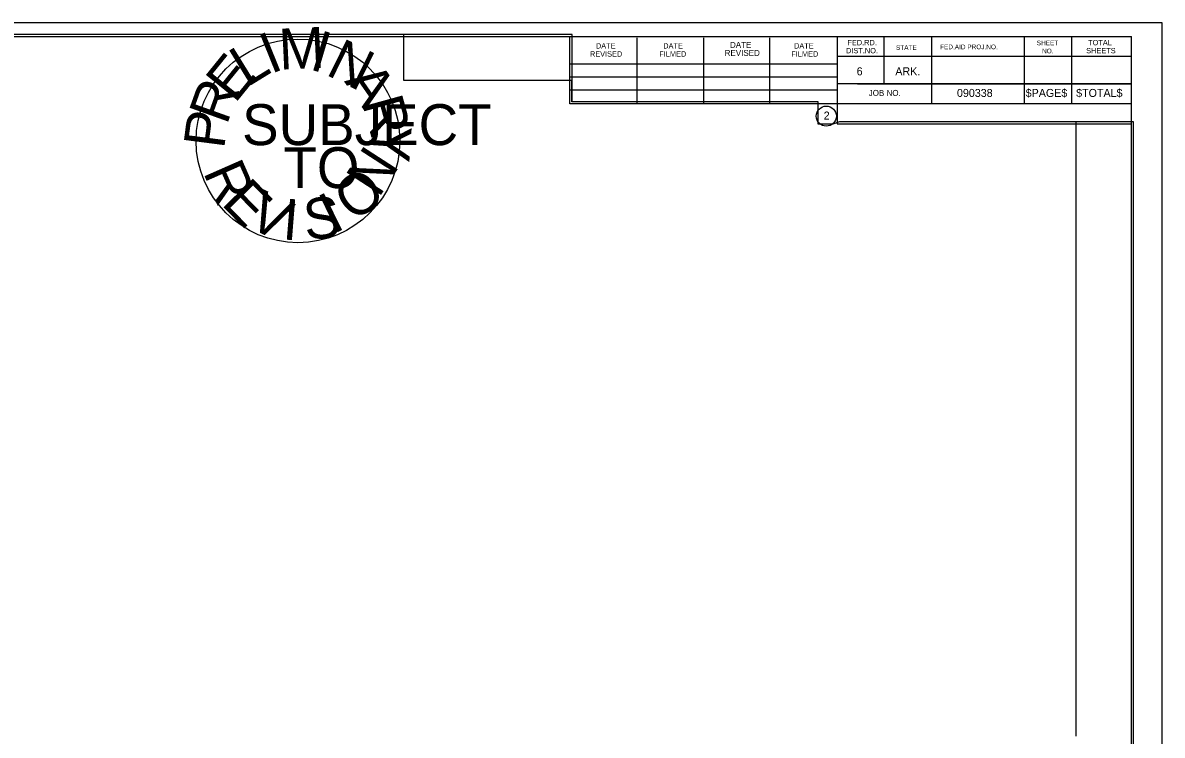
# Model space of a CAD drawing. Extents: x -1.3 to 32, y -0.2 to 20.7.
# Drawn here: x 15.35 to 32.04, y 10.28 to 20.72 of the extents above; entities that cross this region are included whole.
import ezdxf

# ---------------------------------------------------------------- set-up
doc = ezdxf.new("R2010")
doc.units = 0
for name, color, linetype in [('Level 1', 7, 'Continuous'), ('Level 24', 7, 'Continuous'), ('Level 62', 7, 'Continuous'), ('Level 63', 7, 'Continuous'), ('R_Border Prem', 7, 'Continuous')]:
    doc.layers.add(name, color=color, linetype=linetype)

msp = doc.modelspace()

# ---------------------------------------------------------------- linework, layer by layer
at = {"layer": 'Level 1'}
for p, q in [((-0.03, 20.516), (31.588, 20.516)), ((23.362, 19.528), (23.362, 20.516)), ((24.348, 19.528), (24.348, 20.496)), ((25.324, 19.528), (25.324, 20.496)), ((26.292, 19.528), (26.292, 20.496)), ((27.278, 20.516), (27.278, 19.236)), ((27.962, 20.516), (27.962, 19.822)), ((28.656, 20.516), (28.656, 19.528)), ((30.014, 20.516), (30.014, 19.528)), ((30.708, 20.516), (30.708, 19.528)), ((31.588, -0.03), (31.588, 20.516)), ((31.588, 20.222), (27.278, 20.222)), ((31.588, 20.224), (31.588, 20.224)), ((23.362, 20.114), (27.278, 20.114)), ((23.362, 19.928), (27.278, 19.928)), ((23.362, 19.528), (23.362, 19.734)), ((23.362, 19.734), (27.278, 19.734)), ((31.588, 19.822), (27.278, 19.822)), ((27.574, 19.822), (31.588, 19.822)), ((31.588, 19.528), (23.362, 19.528)), ((27.278, 19.236), (31.588, 19.236))]:
    msp.add_line(p, q, dxfattribs=at)
msp.add_circle((27.117, 19.35), 0.147, dxfattribs=at)
at = {"layer": 'Level 24'}
for p, q in [((20.927, 20.545), (0.779, 20.545)), ((20.927, 19.872), (20.927, 20.545)), ((27, 19.233), (27, 19.558)), ((27.212, 19.233), (27, 19.233)), ((27.308, 19.266), (27.212, 19.233)), ((30.779, 19.266), (27.308, 19.266)), ((30.779, 10.264), (30.779, 19.266))]:
    msp.add_line(p, q, dxfattribs=at)
msp.add_lwpolyline([(27, 19.558), (23.391, 19.557), (23.391, 19.872), (20.927, 19.872)], dxfattribs=at)
at = {"layer": 'Level 62'}
for p, q in [((23.392, 20.546), (0, 20.546)), ((23.392, 19.558), (23.392, 20.546)), ((27, 19.558), (23.392, 19.558)), ((27, 19.233), (27, 19.558)), ((27.212, 19.233), (27, 19.233)), ((27.308, 19.266), (27.212, 19.233)), ((31.618, 19.266), (27.308, 19.266)), ((31.618, 10.294), (31.618, 19.266)), ((31.618, 0), (31.618, 10.294))]:
    msp.add_line(p, q, dxfattribs=at)
at = {"layer": 'Level 63'}
msp.add_lwpolyline([(-1.292, -0.229), (32.038, -0.229), (32.038, 20.717), (-1.292, 20.717)], close=True, dxfattribs=at)
at = {"layer": 'R_Border Prem'}
msp.add_circle((19.377, 18.987), 1.492, dxfattribs=at)

# ---------------------------------------------------------------- texts
at = {"layer": 'Level 1'}
for s, height, p in [('DATE', 0.0782, (23.742, 20.34)), ('DATE', 0.0782, (24.728, 20.34)), ('DATE', 0.0879, (25.706, 20.35)), ('DATE', 0.0782, (26.644, 20.34)), ('FED.RD.', 0.0782, (27.426, 20.388)), ('STATE', 0.0684, (28.138, 20.32)), ('FED.AID PROJ.NO.', 0.0684, (28.784, 20.33)), ('SHEET', 0.0684, (30.2, 20.388)), ('TOTAL', 0.0782, (30.952, 20.388)), ('REVISED', 0.0782, (23.654, 20.222)), ('FILMED', 0.0782, (24.67, 20.222)), ('REVISED', 0.0879, (25.628, 20.232)), ('FILMED', 0.0782, (26.604, 20.222)), ('DIST.NO.', 0.0782, (27.406, 20.27)), ('NO.', 0.0684, (30.278, 20.27)), ('SHEETS', 0.0782, (30.924, 20.27)), ('6', 0.117, (27.562, 19.948)), ('ARK.', 0.1172, (28.128, 19.948)), ('JOB NO.', 0.0879, (27.738, 19.646)), ('090338', 0.1172, (29.031, 19.631)), ('$PAGE$', 0.1172, (30.038, 19.631)), ('$TOTAL$', 0.1172, (30.777, 19.631)), ('2', 0.117, (27.079, 19.3))]:
    msp.add_text(s, height=height, dxfattribs=at).set_placement(p)
at = {"layer": 'R_Border Prem'}
for s, rotation, p in [('I', 22.0105, (18.978, 19.963)), ('M', 2.6943, (19.11, 20.029)), ('I', 343.3781, (19.53, 20.041)), ('N', 333.7199, (19.767, 19.964)), ('E', 50.9849, (18.453, 19.525)), ('L', 31.6686, (18.63, 19.766)), ('R', 70.3011, (18.333, 19.208)), ('A', 304.7456, (20.049, 19.861)), ('R', 285.4294, (20.31, 19.556)), ('P', 82.6089, (18.294, 18.859)), ('Y', 266.1131, (20.445, 19.232)), ('N', 57.1378, (20.559, 18.14)), ('R', 293.7639, (17.982, 18.53)), ('E', 314.3262, (18.24, 18.062)), ('O', 36.5754, (20.196, 17.785)), ('V', 334.8885, (18.612, 17.737)), ('I', 26.2943, (19.89, 17.617)), ('I', 355.4508, (19.14, 17.545)), ('S', 5.732, (19.488, 17.534))]:
    msp.add_text(s, height=0.6, rotation=rotation, dxfattribs=at).set_placement(p)
for s, p in [('SUBJECT', (18.558, 18.925)), ('TO', (19.164, 18.295))]:
    msp.add_text(s, height=0.6, dxfattribs=at).set_placement(p)

doc.saveas('drawing.dxf')
